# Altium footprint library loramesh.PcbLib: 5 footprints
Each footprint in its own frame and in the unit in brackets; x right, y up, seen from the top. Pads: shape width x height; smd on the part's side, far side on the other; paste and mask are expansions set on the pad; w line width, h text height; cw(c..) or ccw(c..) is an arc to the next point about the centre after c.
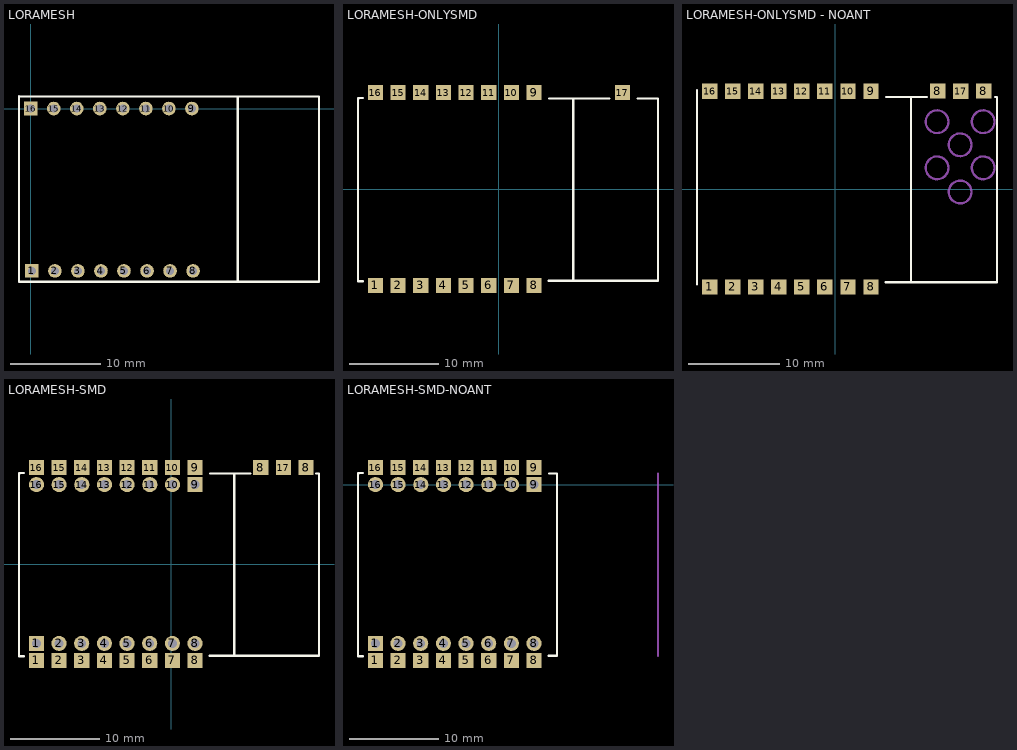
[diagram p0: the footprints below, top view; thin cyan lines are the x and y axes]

## LORAMESH [mm] "Kit LoraMesh"
height 5
pads (16):
  rect 1.5x1.5 hole 0.9: 1(0.127,-17.907) 16(0,0)
  round 1.5 hole 0.9: 2(2.667,-17.907) 3(5.207,-17.907) 4(7.747,-17.907) 5(10.287,-17.907) 6(12.827,-17.907) 7(15.367,-17.907) 8(17.907,-17.907) 9(17.78,0) 10(15.24,0) 11(12.7,0) 12(10.16,0) 13(7.62,0) 14(5.08,0) 15(2.54,0)
Top Overlay:
  lines w0.254: -1.279,1.331 31.8,1.331 31.8,-19.095 -1.281,-19.095 -1.294,-19.081 -1.294,1.344 -1.251,1.3 ; 22.835,-19.03 22.835,1.237
3D body "KIT_LORA.step": height 11.46, standoff -2.34, extent -1.079,-19.926 39.224,1.664

## LORAMESH-ONLYSMD [mm] "Kit LoraMesh"
height 5
pads (17):
  rect 1.7x1.7 smd: 1(-13.843,-10.795) 2(-11.303,-10.795) 3(-8.763,-10.795) 4(-6.223,-10.795) 5(-3.683,-10.795) 6(-1.143,-10.795) 7(1.397,-10.795) 8(3.937,-10.795) 9(3.937,10.795) 10(1.397,10.795) 11(-1.143,10.795) 12(-3.683,10.795) 13(-6.223,10.795) 14(-8.763,10.795) 15(-11.303,10.795) 16(-13.843,10.795) 17(13.843,10.795)
Top Overlay:
  lines w0.254: -15.792,-10.34 -15.241,-10.34 ; -15.792,10.199 -15.241,10.199 ; -15.781,-10.284 -15.794,-10.271 -15.794,10.154 -15.751,10.111 ; 5.548,-10.289 17.821,-10.289 17.821,10.149 15.567,10.149 ; 5.598,10.149 12.361,10.149 ; 8.335,-10.219 8.335,10.047
3D body: height 11.46, standoff -2.34, extent -15.04,-10.615 25.263,10.975

## LORAMESH-ONLYSMD - NOANT [mm] "Kit LoraMesh"
height 5
pads (19):
  rect 1.7x1.7 smd: 1(-13.843,-10.795) 2(-11.303,-10.795) 3(-8.763,-10.795) 4(-6.223,-10.795) 5(-3.683,-10.795) 6(-1.143,-10.795) 7(1.397,-10.795) 8(3.937,-10.795) 8(11.304,10.798) 8(16.384,10.798) 9(3.937,10.795) 10(1.397,10.795) 11(-1.143,10.795) 12(-3.683,10.795) 13(-6.223,10.795) 14(-8.763,10.795) 15(-11.303,10.795) 16(-13.843,10.795) 17(13.843,10.795)
Top Overlay:
  lines w0.254: -15.242,10.918 -15.236,-10.533 ; 5.548,-10.289 17.821,-10.289 17.821,10.149 17.616,10.149 ; 5.598,10.149 10.101,10.149 ; 8.335,-10.219 8.335,10.047
Mechanical 2:
  circle w0.254: c11.219,7.415 r1.251
  circle w0.254: c16.299,7.415 r1.251
  circle w0.254: c16.299,2.335 r1.251
  circle w0.254: c11.219,2.335 r1.251
  circle w0.254: c13.759,4.875 r1.251
  circle w0.254: c13.759,-0.326 r1.251
3D body: height 3.16, standoff -0.01, extent -15.04,-10.615 17.853,10.975

## LORAMESH-SMD [mm] "Kit LoraMesh"
height 5
pads (35):
  rect 1.7x1.7 hole 1: 1(-15.115,-8.896) 9(2.673,8.896)
  rect 1.7x1.7 smd: 1(-15.111,-10.795) 2(-12.571,-10.795) 3(-10.031,-10.795) 4(-7.491,-10.795) 5(-4.951,-10.795) 6(-2.411,-10.795) 7(0.129,-10.795) 8(2.669,-10.795) 8(10.035,10.795) 8(15.115,10.795) 9(2.669,10.795) 10(0.129,10.795) 11(-2.411,10.795) 12(-4.951,10.795) 13(-7.491,10.795) 14(-10.031,10.795) 15(-12.571,10.795) 16(-15.111,10.795) 17(12.575,10.795)
  round 1.7 hole 1: 2(-12.575,-8.896) 3(-10.035,-8.896) 4(-7.495,-8.896) 5(-4.955,-8.896) 6(-2.415,-8.896) 7(0.125,-8.896) 8(2.665,-8.896) 10(0.133,8.896) 11(-2.407,8.896) 12(-4.947,8.896) 13(-7.487,8.896) 14(-10.027,8.896) 15(-12.567,8.896) 16(-15.107,8.896)
Top Overlay:
  lines w0.254: -17.06,-10.34 -16.509,-10.34 ; -17.06,10.199 -16.509,10.199 ; -17.049,-10.284 -17.062,-10.271 -17.062,10.154 -17.019,10.111 ; 4.28,-10.289 16.553,-10.289 16.553,10.149 16.254,10.149 ; 4.33,10.149 8.855,10.149 ; 7.067,-10.219 7.067,10.047
3D body "KIT_LORA.step": height 11.46, standoff -2.34, extent -16.31,-10.685 23.993,10.905

## LORAMESH-SMD-NOANT [mm] "Kit LoraMesh"
height 5
pads (32):
  rect 1.7x1.7 hole 1: 1(35.264,-17.787) 9(53.052,0.005)
  rect 1.7x1.7 smd: 1(35.268,-19.686) 2(37.808,-19.686) 3(40.348,-19.686) 4(42.888,-19.686) 5(45.428,-19.686) 6(47.968,-19.686) 7(50.508,-19.686) 8(53.048,-19.686) 9(53.048,1.904) 10(50.508,1.904) 11(47.968,1.904) 12(45.428,1.904) 13(42.888,1.904) 14(40.348,1.904) 15(37.808,1.904) 16(35.268,1.904)
  round 1.7 hole 1: 2(37.804,-17.787) 3(40.344,-17.787) 4(42.884,-17.787) 5(45.424,-17.787) 6(47.964,-17.787) 7(50.504,-17.787) 8(53.044,-17.787) 10(50.512,0.005) 11(47.972,0.005) 12(45.432,0.005) 13(42.892,0.005) 14(40.352,0.005) 15(37.812,0.005) 16(35.272,0.005)
Top Overlay:
  lines w0.254: 33.319,-19.231 33.87,-19.231 ; 33.319,1.308 33.87,1.308 ; 33.33,-19.175 33.317,-19.162 33.317,1.263 33.36,1.22 ; 54.659,-19.181 55.606,-19.181 55.606,1.258 54.709,1.258
Mechanical 3:
  lines w0.254: 66.932,-19.181 66.932,1.258
3D body: height 11.46, standoff -2.34, extent 13.901,-19.763 54.205,1.827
